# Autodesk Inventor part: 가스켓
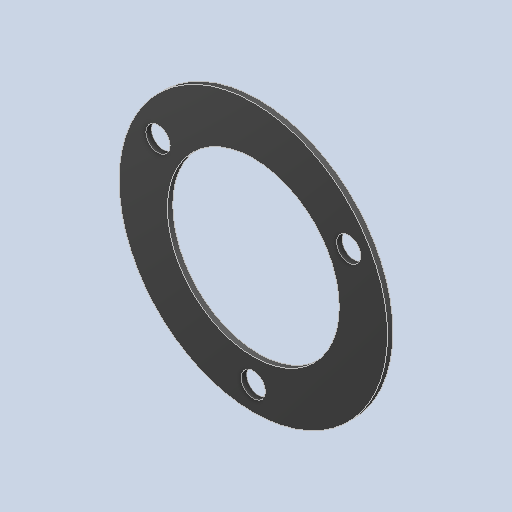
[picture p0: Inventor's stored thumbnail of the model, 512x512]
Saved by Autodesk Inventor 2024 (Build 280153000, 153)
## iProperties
Created: 2025-10
Part Number: 가스켓
Material: 스테인리스스틸
Document SubType Name: Modeling
Designer: EDU03
Density: 8 g/cm^3
Appearance: 기본값
Author: jhkim
Sending System: Autodesk Inventor 2026
Preprocessor: ST-DEVELOPER v20.1
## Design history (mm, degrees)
feature "솔리드1"
node "솔리드2"
